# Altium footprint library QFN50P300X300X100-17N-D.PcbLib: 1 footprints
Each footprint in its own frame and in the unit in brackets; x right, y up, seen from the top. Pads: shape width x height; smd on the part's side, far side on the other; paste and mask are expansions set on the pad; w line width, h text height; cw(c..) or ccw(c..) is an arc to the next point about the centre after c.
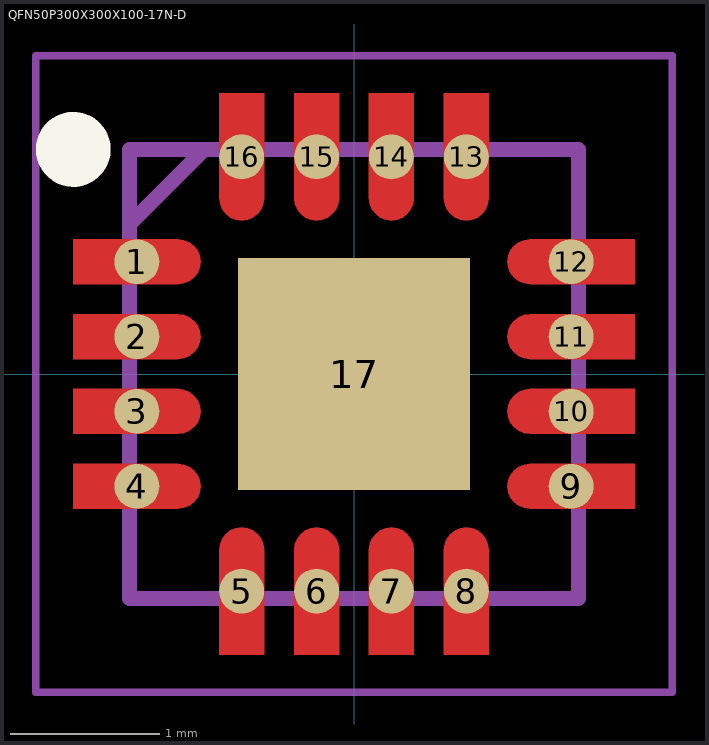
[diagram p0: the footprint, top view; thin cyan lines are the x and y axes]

## QFN50P300X300X100-17N-D [mm]
pads (17):
  round 0.3 smd: 1(-1.45,0.75) 2(-1.45,0.25) 3(-1.45,-0.25) 4(-1.45,-0.75) 5(-0.75,-1.45) 6(-0.25,-1.45) 7(0.25,-1.45) 8(0.75,-1.45) 9(1.45,-0.75) 10(1.45,-0.25) 11(1.45,0.25) 12(1.45,0.75) 13(0.75,1.45) 14(0.25,1.45) 15(-0.25,1.45) 16(-0.75,1.45)
  rect 1.55x1.55 smd: 17(0,0)
L1-Top Layer:
  region: -1.875,0.9 -1.175,0.9 -1.136,0.895 -1.1,0.88 -1.069,0.856 -1.045,0.825 -1.03,0.789 -1.025,0.75 -1.03,0.711 -1.045,0.675 -1.069,0.644 -1.1,0.62 -1.136,0.605 -1.175,0.6 -1.875,0.6
  region: -1.875,0.4 -1.175,0.4 -1.136,0.395 -1.1,0.38 -1.069,0.356 -1.045,0.325 -1.03,0.289 -1.025,0.25 -1.03,0.211 -1.045,0.175 -1.069,0.144 -1.1,0.12 -1.136,0.105 -1.175,0.1 -1.875,0.1
  region: -1.875,-0.1 -1.175,-0.1 -1.136,-0.105 -1.1,-0.12 -1.069,-0.144 -1.045,-0.175 -1.03,-0.211 -1.025,-0.25 -1.03,-0.289 -1.045,-0.325 -1.069,-0.356 -1.1,-0.38 -1.136,-0.395 -1.175,-0.4 -1.875,-0.4
  region: -1.875,-0.6 -1.175,-0.6 -1.136,-0.605 -1.1,-0.62 -1.069,-0.644 -1.045,-0.675 -1.03,-0.711 -1.025,-0.75 -1.03,-0.789 -1.045,-0.825 -1.069,-0.856 -1.1,-0.88 -1.136,-0.895 -1.175,-0.9 -1.875,-0.9
  region: -0.9,-1.875 -0.9,-1.175 -0.895,-1.136 -0.88,-1.1 -0.856,-1.069 -0.825,-1.045 -0.789,-1.03 -0.75,-1.025 -0.711,-1.03 -0.675,-1.045 -0.644,-1.069 -0.62,-1.1 -0.605,-1.136 -0.6,-1.175 -0.6,-1.875
  region: -0.4,-1.875 -0.4,-1.175 -0.395,-1.136 -0.38,-1.1 -0.356,-1.069 -0.325,-1.045 -0.289,-1.03 -0.25,-1.025 -0.211,-1.03 -0.175,-1.045 -0.144,-1.069 -0.12,-1.1 -0.105,-1.136 -0.1,-1.175 -0.1,-1.875
  region: 0.1,-1.875 0.1,-1.175 0.105,-1.136 0.12,-1.1 0.144,-1.069 0.175,-1.045 0.211,-1.03 0.25,-1.025 0.289,-1.03 0.325,-1.045 0.356,-1.069 0.38,-1.1 0.395,-1.136 0.4,-1.175 0.4,-1.875
  region: 0.6,-1.875 0.6,-1.175 0.605,-1.136 0.62,-1.1 0.644,-1.069 0.675,-1.045 0.711,-1.03 0.75,-1.025 0.789,-1.03 0.825,-1.045 0.856,-1.069 0.88,-1.1 0.895,-1.136 0.9,-1.175 0.9,-1.875
  region: 1.875,-0.9 1.175,-0.9 1.136,-0.895 1.1,-0.88 1.069,-0.856 1.045,-0.825 1.03,-0.789 1.025,-0.75 1.03,-0.711 1.045,-0.675 1.069,-0.644 1.1,-0.62 1.136,-0.605 1.175,-0.6 1.875,-0.6
  region: 1.875,-0.4 1.175,-0.4 1.136,-0.395 1.1,-0.38 1.069,-0.356 1.045,-0.325 1.03,-0.289 1.025,-0.25 1.03,-0.211 1.045,-0.175 1.069,-0.144 1.1,-0.12 1.136,-0.105 1.175,-0.1 1.875,-0.1
  region: 1.875,0.1 1.175,0.1 1.136,0.105 1.1,0.12 1.069,0.144 1.045,0.175 1.03,0.211 1.025,0.25 1.03,0.289 1.045,0.325 1.069,0.356 1.1,0.38 1.136,0.395 1.175,0.4 1.875,0.4
  region: 1.875,0.6 1.175,0.6 1.136,0.605 1.1,0.62 1.069,0.644 1.045,0.675 1.03,0.711 1.025,0.75 1.03,0.789 1.045,0.825 1.069,0.856 1.1,0.88 1.136,0.895 1.175,0.9 1.875,0.9
  region: 0.9,1.875 0.9,1.175 0.895,1.136 0.88,1.1 0.856,1.069 0.825,1.045 0.789,1.03 0.75,1.025 0.711,1.03 0.675,1.045 0.644,1.069 0.62,1.1 0.605,1.136 0.6,1.175 0.6,1.875
  region: 0.4,1.875 0.4,1.175 0.395,1.136 0.38,1.1 0.356,1.069 0.325,1.045 0.289,1.03 0.25,1.025 0.211,1.03 0.175,1.045 0.144,1.069 0.12,1.1 0.105,1.136 0.1,1.175 0.1,1.875
  region: -0.1,1.875 -0.1,1.175 -0.105,1.136 -0.12,1.1 -0.144,1.069 -0.175,1.045 -0.211,1.03 -0.25,1.025 -0.289,1.03 -0.325,1.045 -0.356,1.069 -0.38,1.1 -0.395,1.136 -0.4,1.175 -0.4,1.875
  region: -0.6,1.875 -0.6,1.175 -0.605,1.136 -0.62,1.1 -0.644,1.069 -0.675,1.045 -0.711,1.03 -0.75,1.025 -0.789,1.03 -0.825,1.045 -0.856,1.069 -0.88,1.1 -0.895,1.136 -0.9,1.175 -0.9,1.875
Top Overlay:
  circle w0.25: c-1.875,1.5 r0.125
Mechanical 15:
  lines w0.1: -1.5,1 -1,1.5 ; -1.5,-1.5 1.5,-1.5 1.5,1.5 -1.5,1.5 -1.5,-1.5
Mechanical 20:
  lines w0.05: -2.125,-2.125 2.125,-2.125 2.125,2.125 -2.125,2.125 -2.125,-2.125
